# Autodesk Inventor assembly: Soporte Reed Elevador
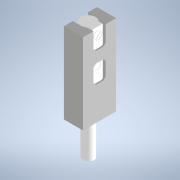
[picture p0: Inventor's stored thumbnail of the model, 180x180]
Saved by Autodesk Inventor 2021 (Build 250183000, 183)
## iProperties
Created: 2021-03
Part Number: Soporte Reed Elevador
Document SubType Name: Assembly
Designer: ATOUZA
Author: ATOUZA
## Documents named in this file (3)
- D:\01 Paralaia\Grupos de Traballo\GT Maquetas\CAD 3D\E_Medida\Soportes Reed DM9B\Soporte Reed Elevador.iam
- D:\01 Paralaia\Grupos de Traballo\GT Maquetas\CAD 3D\E_Medida\Soportes Reed DM9B\D-M9B.ipt
- D:\01 Paralaia\Grupos de Traballo\GT Maquetas\CAD 3D\E_Medida\Soportes Reed DM9B\Soporte Reed Elevador.ipt
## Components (2 placed, 2 different names)
1. D-M9B:1
2. Soporte Reed Elevador:1
